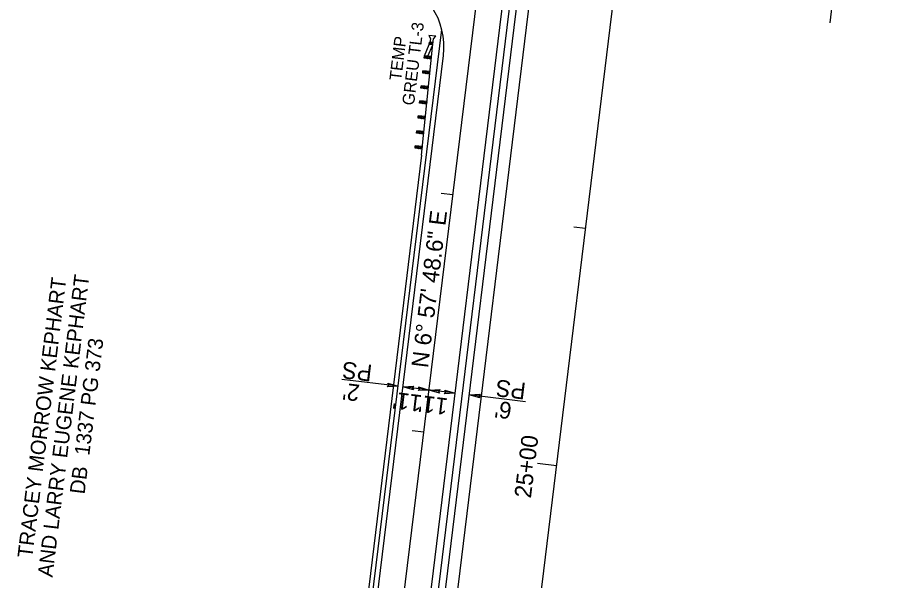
# Model space of a CAD drawing. Extents: x 473658 to 481584, y 489119 to 506230.
# Drawn here: x 481102.3 to 481466.4, y 490536.4 to 490771.8 of the extents above; entities that cross this region are included whole.
import ezdxf

# ---------------------------------------------------------------- set-up
doc = ezdxf.new("R2010")
doc.units = 0
for name, color, linetype in [('Default', 7, 'Continuous'), ('Exist Horizontal Alignment', 7, 'Continuous'), ('Exist Structure Minor Culvert Topo', 7, 'Continuous'), ('Exist Structure Minor Pipes CMP 60 Inch', 7, 'Continuous'), ('Prop Conc Barrier', 7, 'Continuous'), ('Prop Dimension', 7, 'Continuous'), ('Prop EOT', 7, 'Continuous'), ('Prop Guardrail', 7, 'Continuous'), ('Prop Guardrail Anchor Unit CELL', 7, 'Continuous'), ('Prop Horizontal Alignment', 7, 'Continuous'), ('Prop Horizontal Alignment Direction Label', 7, 'Continuous'), ('Prop Horizontal Alignment Station Label', 7, 'Continuous'), ('Prop Horizontal Alignment Tick Label', 7, 'Continuous'), ('Prop Horizontal Alignment Tick Large', 7, 'Continuous'), ('Prop Horizontal Alignment Tick Small', 7, 'Continuous'), ('Prop Paved Shoulder', 7, 'Continuous'), ('Scratch_Level_5', 7, 'Continuous'), ('Sheet Profile Grid Major CELL', 7, 'Continuous')]:
    doc.layers.add(name, color=color, linetype=linetype)

msp = doc.modelspace()

# ---------------------------------------------------------------- linework, layer by layer
at = {"layer": 'Exist Horizontal Alignment'}
for points in [[(481257.08, 490618.96), (481261.46, 490617.64), (481256.87, 490617.4), (481257.54, 490618.12)], [(481267.77, 490616.1), (481263.4, 490617.41), (481267.99, 490617.66), (481267.32, 490616.94)], [(481269.95, 490617.4), (481274.32, 490616.08), (481269.73, 490615.84), (481270.4, 490616.56)], [(481278.69, 490614.77), (481274.32, 490616.08), (481278.91, 490616.33), (481278.24, 490615.6)], [(481280.91, 490616.05), (481285.28, 490614.73), (481280.69, 490614.49), (481281.36, 490615.21)], [(481295.52, 490612.76), (481291.14, 490614.07), (481295.73, 490614.32), (481295.06, 490613.59)]]:
    msp.add_lwpolyline(points, close=True, dxfattribs=at)
at = {"layer": 'Exist Structure Minor Pipes CMP 60 Inch'}
msp.add_line((481254.45, 490271.98), (481344.18, 491006.64), dxfattribs=at)
at = {"layer": 'Prop Conc Barrier'}
msp.add_line((481218.72, 490045.39), (481336.24, 491007.62), dxfattribs=at)
at = {"layer": 'Prop Dimension'}
for p, q in [((481261.41, 490617.66), (481237.85, 490620.53)), ((481285.24, 490614.73), (481263.4, 490617.41)), ((481314.65, 490611.15), (481291.14, 490614.07))]:
    msp.add_line(p, q, dxfattribs=at)
at = {"layer": 'Prop EOT'}
for p, q in [((481195.32, 489878.54), (481333.26, 491007.97)), ((481221.63, 490275.44), (481280.31, 490755.9))]:
    msp.add_line(p, q, dxfattribs=at)
msp.add_arc((481250.54, 490759.54), 30, 353.0365, 73.6818, dxfattribs=at)
at = {"layer": 'Prop Guardrail'}
msp.add_line((481271.2, 490714.29), (481223.47, 490323.45), dxfattribs=at)
at = {"layer": 'Prop Guardrail Anchor Unit CELL'}
for p, q in [((481277.11, 490763.94), (481274.19, 490764.29)), ((481274.19, 490764.29), (481274.9, 490763.02)), ((481276.11, 490762.88), (481277.11, 490763.94)), ((481271.2, 490714.29), (481275.94, 490760.8)), ((481272.35, 490755.74), (481274.4, 490760.46)), ((481273.87, 490755.59), (481275.89, 490760.31)), ((481274.4, 490760.46), (481274.5, 490761.45)), ((481275.99, 490761.3), (481274.4, 490760.46)), ((481274.4, 490760.46), (481274.45, 490760.96)), ((481275.89, 490760.31), (481274.4, 490760.46)), ((481275.99, 490761.3), (481274.5, 490761.45)), ((481274.5, 490761.45), (481275.89, 490760.31)), ((481274.9, 490763.02), (481274.66, 490760.99)), ((481274.66, 490760.99), (481275.26, 490760.92)), ((481275.26, 490760.92), (481275.87, 490760.84)), ((481275.87, 490760.84), (481276.11, 490762.88)), ((481272.24, 490754.75), (481272.35, 490755.74)), ((481273.87, 490755.59), (481272.24, 490754.75)), ((481275.29, 490754.44), (481272.24, 490754.75)), ((481275.39, 490755.43), (481272.35, 490755.74)), ((481272.35, 490755.74), (481273.77, 490754.59)), ((481273.77, 490754.59), (481273.87, 490755.59)), ((481273.77, 490754.59), (481275.39, 490755.43)), ((481275.29, 490754.44), (481273.87, 490755.59)), ((481271.67, 490748.47), (481271.77, 490749.47)), ((481273.26, 490749.31), (481271.67, 490748.47)), ((481274.75, 490749.16), (481271.77, 490749.47)), ((481271.77, 490749.47), (481273.16, 490748.32)), ((481273.16, 490748.32), (481273.26, 490749.31)), ((481273.16, 490748.32), (481274.75, 490749.16)), ((481274.65, 490748.17), (481273.26, 490749.31)), ((481274.65, 490748.17), (481271.67, 490748.47)), ((481270.89, 490742.22), (481270.99, 490743.21)), ((481272.56, 490743.05), (481270.89, 490742.22)), ((481274.01, 490741.9), (481270.89, 490742.22)), ((481274.12, 490742.89), (481270.99, 490743.21)), ((481270.99, 490743.21), (481272.45, 490742.06)), ((481272.45, 490742.06), (481272.56, 490743.05)), ((481272.45, 490742.06), (481274.12, 490742.89)), ((481274.01, 490741.9), (481272.56, 490743.05)), ((481270.36, 490735.94), (481270.46, 490736.93)), ((481271.97, 490736.78), (481270.36, 490735.94)), ((481273.38, 490735.63), (481270.36, 490735.94)), ((481273.48, 490736.62), (481270.46, 490736.93)), ((481270.46, 490736.93), (481271.87, 490735.78)), ((481271.87, 490735.78), (481271.97, 490736.78)), ((481271.87, 490735.78), (481273.48, 490736.62)), ((481273.38, 490735.63), (481271.97, 490736.78)), ((481273.38, 490735.63), (481273.48, 490736.62)), ((481269.71, 490729.67), (481269.81, 490730.66)), ((481271.32, 490730.51), (481269.71, 490729.67)), ((481272.74, 490729.36), (481269.71, 490729.67)), ((481272.84, 490730.36), (481269.81, 490730.66)), ((481269.81, 490730.66), (481271.22, 490729.52)), ((481271.22, 490729.52), (481271.32, 490730.51)), ((481271.22, 490729.52), (481272.84, 490730.36)), ((481272.74, 490729.36), (481271.32, 490730.51)), ((481269.06, 490723.4), (481269.16, 490724.4)), ((481270.68, 490724.24), (481269.06, 490723.4)), ((481272.2, 490724.09), (481269.16, 490724.4)), ((481269.16, 490724.4), (481270.58, 490723.25)), ((481270.58, 490723.25), (481270.68, 490724.24)), ((481270.58, 490723.25), (481272.2, 490724.09)), ((481272.1, 490723.09), (481270.68, 490724.24)), ((481272.1, 490723.09), (481269.06, 490723.4)), ((481268.48, 490717.13), (481268.58, 490718.12)), ((481270.07, 490717.97), (481268.48, 490717.13)), ((481271.46, 490716.82), (481268.48, 490717.13)), ((481271.56, 490717.82), (481268.58, 490718.12)), ((481268.58, 490718.12), (481269.97, 490716.97)), ((481269.97, 490716.97), (481270.07, 490717.97)), ((481269.97, 490716.97), (481271.56, 490717.82)), ((481271.56, 490717.82), (481270.07, 490717.97)), ((481270.07, 490717.97), (481271.46, 490716.82)), ((481271.46, 490716.82), (481271.56, 490717.82))]:
    msp.add_line(p, q, dxfattribs=at)
at = {"layer": 'Prop Horizontal Alignment'}
for p, q in [((481200.24, 489541.46), (481402.27, 491195.58)), ((481184.4, 489879.88), (481322.35, 491009.3))]:
    msp.add_line(p, q, dxfattribs=at)
at = {"layer": 'Prop Horizontal Alignment Station Label'}
msp.add_line((481466.38, 490970.79), (481441.81, 490769.61), dxfattribs=at)
at = {"layer": 'Prop Horizontal Alignment Tick Large'}
msp.add_line((481327.61, 490584.35), (481319.67, 490585.32), dxfattribs=at)
at = {"layer": 'Prop Horizontal Alignment Tick Small'}
for p, q in [((481284.29, 490697.69), (481279.32, 490698.29)), ((481339.74, 490683.62), (481334.77, 490684.22)), ((481272.16, 490598.42), (481267.2, 490599.03))]:
    msp.add_line(p, q, dxfattribs=at)
at = {"layer": 'Prop Paved Shoulder'}
for p, q in [((481221.7, 490045.03), (481339.22, 491007.26)), ((481218.92, 490269.72), (481279.63, 490766.83))]:
    msp.add_line(p, q, dxfattribs=at)
at = {"layer": 'Scratch_Level_5'}
msp.add_line((481201.27, 489877.82), (481339.22, 491007.24), dxfattribs=at)

# ---------------------------------------------------------------- texts
at = {"layer": 'Default'}
for s, p in [('TRACEY MORROW KEPHART', (481108.46, 490545.66)), ('AND LARRY EUGENE KEPHART', (481116.92, 490537.63)), ('DB  1337 PG 373', (481130.33, 490572.34))]:
    msp.add_text(s, height=6.25, rotation=83.0365, dxfattribs=at).set_placement(p)
at = {"layer": 'Exist Structure Minor Culvert Topo'}
for s, p in [('GREU TL-3', (481268, 490734.85)), ('TEMP', (481262.66, 490745.19))]:
    msp.add_text(s, height=5, rotation=83.0365, dxfattribs=at).set_placement(p)
at = {"layer": 'Prop Horizontal Alignment Direction Label'}
msp.add_text('N 6%%d 57\' 48.6" E', height=7, rotation=83.0365, dxfattribs=at).set_placement((481273.86, 490625.11))
at = {"layer": 'Prop Horizontal Alignment Tick Label'}
msp.add_text('25+00', height=7, rotation=83.0365, dxfattribs=at).set_placement((481316.87, 490570.67))
at = {"layer": 'Sheet Profile Grid Major CELL'}
for s, p in [('PS', (481250.86, 490626.53)), ("2'", (481245.62, 490618.23)), ('PS', (481315.09, 490619.01)), ("11'", (481271.68, 490613.85)), ("11'", (481282.5, 490612.52)), ("6'", (481309.2, 490610.79))]:
    msp.add_text(s, height=7, rotation=173.0365, dxfattribs=at).set_placement(p)

doc.saveas('drawing.dxf')
